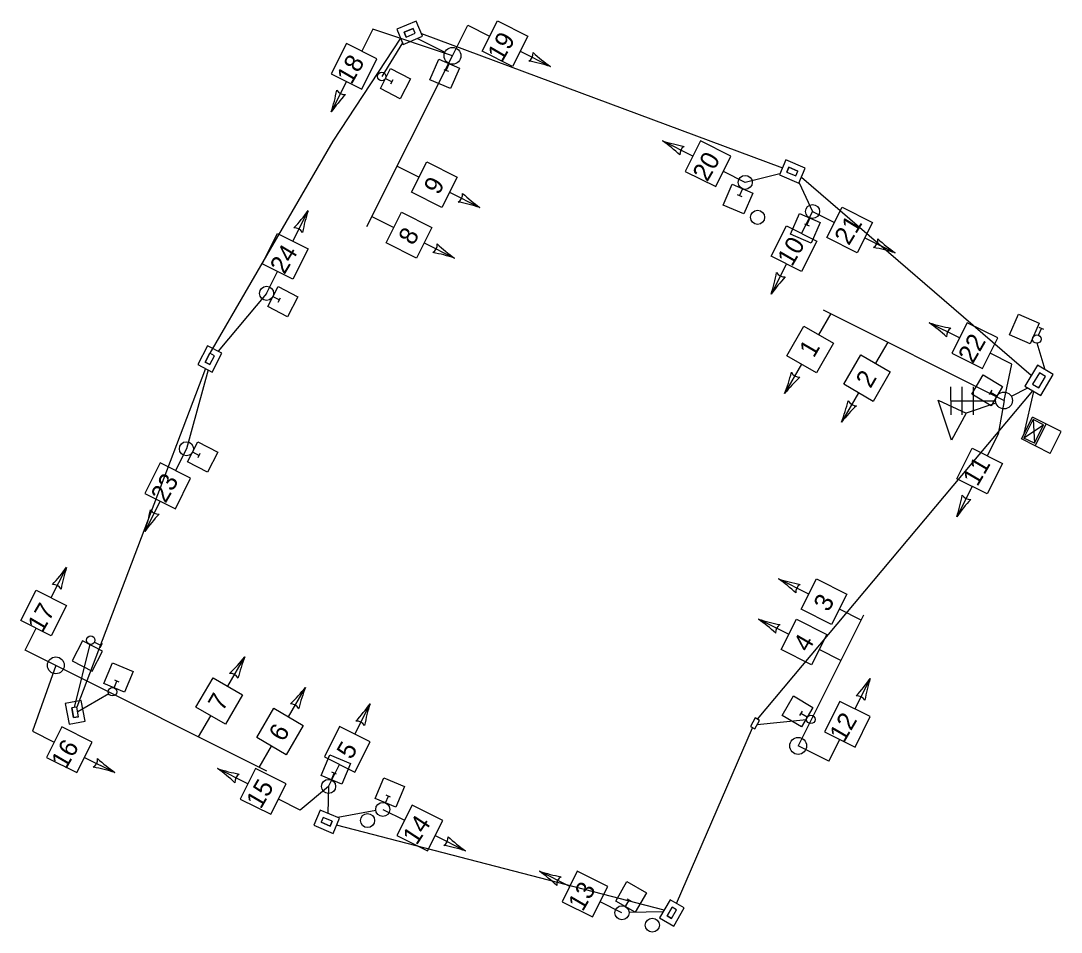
# Model space of a CAD drawing. Extents: x 998065 to 998820, y 1984965 to 1986752.
# Drawn here: x 998635.3 to 998820.4, y 1984965.1 to 1985127.2 of the extents above; entities that cross this region are included whole.
import ezdxf

# ---------------------------------------------------------------- set-up
doc = ezdxf.new("R2010")
doc.units = 0
for name, color, linetype in [('EX_ROW_Annotation', 7, 'Continuous'), ('S_CURB', 7, 'Continuous'), ('S_DRIVEWAY', 7, 'Continuous'), ('S_EDGE_PAVEMENT', 7, 'Continuous'), ('S_PAVEMENT_CROWN', 7, 'Continuous'), ('S_SHOULDER', 7, 'Continuous'), ('S_SIDEWALK', 7, 'Continuous'), ('S_WALL', 7, 'Continuous')]:
    doc.layers.add(name, color=color, linetype=linetype)

msp = doc.modelspace()

# ---------------------------------------------------------------- linework, layer by layer
at = {"layer": 'EX_ROW_Annotation'}
for centre in [(998766.4, 1985092.21), (998696.98, 1984984.92), (998747.66, 1984966.31)]:
    msp.add_circle(centre, 1.25, dxfattribs=at)
at = {"layer": 'S_CURB'}
for p, q in [((998813.35, 1985052.8), (998815.29, 1985056.67)), ((998813.79, 1985052.95), (998815.44, 1985056.23)), ((998820.42, 1985054.1), (998815.29, 1985056.67)), ((998815.44, 1985056.23), (998815.65, 1985052.02)), ((998817.3, 1985055.3), (998815.44, 1985056.23)), ((998813.8, 1985052.97), (998817.3, 1985055.3)), ((998815.65, 1985052.02), (998817.3, 1985055.3)), ((998815.8, 1985051.57), (998817.74, 1985055.44)), ((998818.48, 1985050.23), (998820.42, 1985054.1)), ((998818.48, 1985050.23), (998813.35, 1985052.8)), ((998815.65, 1985052.02), (998813.79, 1985052.95))]:
    msp.add_line(p, q, dxfattribs=at)
at = {"layer": 'S_DRIVEWAY'}
for p, q in [((998706.57, 1985124.9), (998770.84, 1985101.04)), ((998703.2, 1985123.23), (998699.51, 1985117.26)), ((998705.85, 1985124.03), (998710.75, 1985121.61)), ((998770.37, 1985099.97), (998764.19, 1985098.43)), ((998773.77, 1985098.37), (998776.18, 1985093.25)), ((998815.08, 1985064.05), (998774.18, 1985099.32)), ((998679.02, 1985078.69), (998670.38, 1985068.38)), ((998817.6, 1985065.07), (998816.14, 1985069.81)), ((998668.12, 1985065.33), (998645.23, 1985005.11)), ((998668.64, 1985065.06), (998664.74, 1985051.05)), ((998766.35, 1985002.96), (998815.37, 1985061.35)), ((998811.56, 1985060.38), (998814.48, 1985061.88)), ((998813.82, 1985053.74), (998815.57, 1985061.23)), ((998647.53, 1985016.27), (998644.78, 1985005.03)), ((998650.94, 1985007.45), (998645.4, 1985004.25)), ((998775.11, 1985002.84), (998766.34, 1985001.97)), ((998751.98, 1984970.17), (998765.51, 1985001.42)), ((998690.05, 1984990.99), (998689.91, 1984986.19)), ((998698.46, 1984986.68), (998691.67, 1984985.45)), ((998749.76, 1984969), (998691.48, 1984984.1)), ((998749.57, 1984968.69), (998743.51, 1984968.55))]:
    msp.add_line(p, q, dxfattribs=at)
msp.add_lwpolyline([(998702.84, 1985124.09), (998690.82, 1985105.74), (998668.9, 1985068.02)], dxfattribs=at)
at = {"layer": 'S_EDGE_PAVEMENT'}
for p, q in [((998696.85, 1985090.55), (998712.1, 1985120.94)), ((998778.07, 1985075.77), (998810.25, 1985059.64)), ((998785.27, 1985021.43), (998773.62, 1984998.19)), ((998679.04, 1984993.7), (998641.5, 1985012.52))]:
    msp.add_line(p, q, dxfattribs=at)
for centre, radius in [((998712.1, 1985120.94), 1.5), ((998699.51, 1985117.26), 0.75), ((998764.19, 1985098.43), 1.25), ((998776.18, 1985093.25), 1.25), ((998679.02, 1985078.69), 1.25), ((998816.09, 1985070.56), 0.75), ((998810.25, 1985059.64), 1.5), ((998664.74, 1985051.05), 1.25), ((998647.71, 1985017), 0.75), ((998641.5, 1985012.52), 1.5), ((998651.59, 1985007.82), 0.75), ((998775.86, 1985002.91), 0.75), ((998773.62, 1984998.19), 1.5), ((998690.05, 1984990.99), 1.25), ((998699.69, 1984986.9), 1.25), ((998742.26, 1984968.52), 1.25)]:
    msp.add_circle(centre, radius, dxfattribs=at)
at = {"layer": 'S_PAVEMENT_CROWN'}
for p, q in [((998712.1, 1985120.94), (998714.82, 1985126.4)), ((998714.82, 1985126.4), (998718.7, 1985124.44)), ((998697.9, 1985125.66), (998695.96, 1985121.77)), ((998712.1, 1985120.94), (998697.9, 1985125.66)), ((998724.13, 1985121.74), (998729.53, 1985119.02)), ((998693.23, 1985116.36), (998690.53, 1985110.96)), ((998754.89, 1985103.1), (998749.49, 1985105.8)), ((998702.27, 1985101.33), (998706.15, 1985099.38)), ((998764.19, 1985098.43), (998760.3, 1985100.37)), ((998711.58, 1985096.67), (998716.98, 1985093.96)), ((998683.68, 1985088), (998686.39, 1985093.39)), ((998776.18, 1985093.25), (998774.22, 1985089.37)), ((998776.18, 1985093.25), (998780.06, 1985091.3)), ((998697.75, 1985092.34), (998701.63, 1985090.38)), ((998707.06, 1985087.68), (998712.46, 1985084.96)), ((998785.48, 1985088.59), (998790.88, 1985085.88)), ((998771.52, 1985083.94), (998768.8, 1985078.55)), ((998679.02, 1985078.69), (998680.97, 1985082.57)), ((998779.44, 1985075.09), (998777.26, 1985071.33)), ((998802.35, 1985070.76), (998796.95, 1985073.46)), ((998789.56, 1985070.02), (998787.37, 1985066.26)), ((998811.65, 1985066.09), (998807.76, 1985068.03)), ((998774.23, 1985066.08), (998771.2, 1985060.85)), ((998810.25, 1985059.64), (998811.65, 1985066.09)), ((998784.35, 1985061), (998781.31, 1985055.78)), ((998810.25, 1985059.64), (998809.21, 1985053.67)), ((998809.21, 1985053.67), (998807.25, 1985049.78)), ((998664.74, 1985051.05), (998662.8, 1985047.16)), ((998804.55, 1985044.36), (998801.83, 1985038.96)), ((998660.07, 1985041.75), (998657.37, 1985036.35)), ((998640.7, 1985024.56), (998643.42, 1985029.95)), ((998775.52, 1985025.19), (998770.12, 1985027.91)), ((998784.82, 1985020.53), (998780.94, 1985022.49)), ((998771.92, 1985018.04), (998766.53, 1985020.76)), ((998636.04, 1985015.25), (998638, 1985019.13)), ((998641.5, 1985012.52), (998636.04, 1985015.25)), ((998781.23, 1985013.39), (998777.35, 1985015.34)), ((998672.1, 1985008.8), (998675.13, 1985014.02)), ((998641.5, 1985012.52), (998637.33, 1985000.82)), ((998783.75, 1985004.76), (998786.45, 1985010.17)), ((998682.91, 1985003.38), (998685.94, 1985008.6)), ((998694.72, 1985000.29), (998697.42, 1985005.69)), ((998666.89, 1984999.79), (998669.07, 1985003.55)), ((998637.33, 1985000.82), (998641.21, 1984998.88)), ((998779.07, 1984995.46), (998781.01, 1984999.35)), ((998677.7, 1984994.37), (998679.88, 1984998.13)), ((998779.07, 1984995.46), (998773.62, 1984998.19)), ((998646.63, 1984996.15), (998652.03, 1984993.45)), ((998690.05, 1984990.99), (998691.99, 1984994.88)), ((998675.7, 1984991.46), (998670.29, 1984994.16)), ((998690.05, 1984990.99), (998685, 1984986.78)), ((998685, 1984986.78), (998681.11, 1984988.72)), ((998699.69, 1984986.9), (998703.58, 1984984.96)), ((998708.99, 1984982.23), (998714.39, 1984979.53)), ((998732.96, 1984973.19), (998727.56, 1984975.89)), ((998742.26, 1984968.52), (998738.37, 1984970.46))]:
    msp.add_line(p, q, dxfattribs=at)
for points in [[(998717.35, 1985121.75), (998720.08, 1985127.16), (998725.49, 1985124.44), (998722.76, 1985119.02)], [(998698.66, 1985120.42), (998693.23, 1985123.14), (998690.52, 1985117.71), (998695.95, 1985115)], [(998758.95, 1985097.67), (998761.66, 1985103.1), (998756.24, 1985105.81), (998753.53, 1985100.38)], [(998704.8, 1985096.68), (998707.52, 1985102.1), (998712.94, 1985099.37), (998710.21, 1985093.96)], [(998700.28, 1985087.69), (998703, 1985093.11), (998708.42, 1985090.38), (998705.69, 1985084.96)], [(998778.7, 1985088.6), (998781.43, 1985094.02), (998786.84, 1985091.29), (998784.12, 1985085.88)], [(998683.67, 1985081.22), (998678.25, 1985083.94), (998680.98, 1985089.36), (998686.39, 1985086.63)], [(998771.53, 1985090.72), (998776.94, 1985088), (998774.22, 1985082.58), (998768.8, 1985085.31)], [(998774.65, 1985072.85), (998779.89, 1985069.8), (998776.85, 1985064.56), (998771.6, 1985067.6)], [(998806.41, 1985065.33), (998809.12, 1985070.76), (998803.7, 1985073.47), (998800.99, 1985068.04)], [(998784.76, 1985067.77), (998790.01, 1985064.73), (998786.96, 1985059.48), (998781.72, 1985062.53)], [(998804.56, 1985051.14), (998809.98, 1985048.41), (998807.25, 1985043), (998801.83, 1985045.72)], [(998665.5, 1985045.82), (998660.07, 1985048.53), (998657.36, 1985043.1), (998662.79, 1985040.39)], [(998782.3, 1985025.18), (998779.57, 1985019.77), (998774.16, 1985022.49), (998776.88, 1985027.91)], [(998640.69, 1985017.78), (998635.27, 1985020.5), (998638, 1985025.92), (998643.42, 1985023.19)], [(998778.7, 1985018.03), (998775.98, 1985012.62), (998770.56, 1985015.34), (998773.29, 1985020.76)], [(998671.68, 1985002.03), (998666.44, 1985005.08), (998669.48, 1985010.32), (998674.73, 1985007.27)], [(998778.32, 1985000.7), (998783.74, 1984997.99), (998786.45, 1985003.41), (998781.03, 1985006.12)], [(998682.49, 1984996.61), (998677.25, 1984999.66), (998680.29, 1985004.9), (998685.54, 1985001.85)], [(998642.56, 1985001.58), (998639.85, 1984996.15), (998645.27, 1984993.44), (998647.99, 1984998.87)], [(998689.29, 1984996.22), (998694.72, 1984993.51), (998697.43, 1984998.94), (998692, 1985001.65)], [(998679.76, 1984986.03), (998682.47, 1984991.45), (998677.05, 1984994.16), (998674.34, 1984988.74)], [(998704.92, 1984987.66), (998702.21, 1984982.23), (998707.64, 1984979.52), (998710.35, 1984984.95)], [(998737.02, 1984967.76), (998739.73, 1984973.19), (998734.31, 1984975.9), (998731.6, 1984970.47)]]:
    msp.add_lwpolyline(points, close=True, dxfattribs=at)
for centre, radius, start, end in [((998724.82, 1985121.39), 1.63, 301.4366, 5.1312), ((998746.57, 1985143.07), 29.47, 226.9375, 234.6756), ((998720.37, 1985091.01), 29.47, 71.8922, 79.6303), ((998662.49, 1985120.04), 29.47, 342.0542, 349.7923), ((998714.62, 1985093.98), 29.47, 137.0994, 144.8375), ((998692.88, 1985115.67), 1.63, 211.5985, 275.2932), ((998732.51, 1985081.71), 29.47, 47.0994, 54.8375), ((998758.57, 1985133.84), 29.47, 252.0542, 259.7923), ((998754.2, 1985103.45), 1.63, 121.5985, 185.2932), ((998712.27, 1985096.32), 1.63, 301.4366, 5.1312), ((998734.02, 1985118), 29.47, 226.9375, 234.6756), ((998707.82, 1985065.94), 29.47, 71.8922, 79.6303), ((998662.35, 1985110.44), 29.47, 316.9375, 324.6756), ((998714.41, 1985084.23), 29.47, 161.8922, 169.6303), ((998684.03, 1985088.69), 1.63, 31.4366, 95.1312), ((998707.75, 1985087.33), 1.63, 301.4366, 5.1312), ((998729.5, 1985109.01), 29.47, 226.9375, 234.6756), ((998786.18, 1985088.24), 1.63, 301.4366, 5.1312), ((998807.92, 1985109.92), 29.47, 226.9375, 234.6756), ((998703.3, 1985056.95), 29.47, 71.8922, 79.6303), ((998781.72, 1985057.86), 29.47, 71.8922, 79.6303), ((998740.79, 1985087.71), 29.47, 341.8922, 349.6303), ((998792.85, 1985061.5), 29.47, 136.9375, 144.6756), ((998771.17, 1985083.25), 1.63, 211.4366, 275.1312), ((998779.97, 1985049.37), 29.47, 47.0994, 54.8375), ((998806.03, 1985101.5), 29.47, 252.0542, 259.7923), ((998801.66, 1985071.11), 1.63, 121.5985, 185.2932), ((998743.79, 1985071.68), 29.47, 338.4472, 346.1853), ((998794.18, 1985042.4), 29.47, 133.4924, 141.2306), ((998773.84, 1985065.41), 1.63, 207.9916, 271.6862), ((998753.9, 1985066.61), 29.47, 338.4472, 346.1853), ((998783.96, 1985060.33), 1.63, 207.9916, 271.6862), ((998804.29, 1985037.33), 29.47, 133.4924, 141.2306), ((998773.82, 1985048.12), 29.47, 341.8922, 349.6303), ((998804.2, 1985043.67), 1.63, 211.4366, 275.1312), ((998825.88, 1985021.92), 29.47, 136.9375, 144.6756), ((998629.33, 1985045.43), 29.47, 342.0542, 349.7923), ((998681.46, 1985019.37), 29.47, 137.0994, 144.8375), ((998659.72, 1985041.06), 1.63, 211.5985, 275.2932), ((998619.37, 1985047), 29.47, 316.9375, 324.6756), ((998671.43, 1985020.79), 29.47, 161.8922, 169.6303), ((998779.28, 1985055.92), 29.47, 251.8922, 259.6303), ((998753.08, 1985003.86), 29.47, 46.9375, 54.6756), ((998641.05, 1985025.25), 1.63, 31.4366, 95.1312), ((998774.82, 1985025.54), 1.63, 121.4366, 185.1312), ((998775.69, 1985048.77), 29.47, 251.8922, 259.6303), ((998749.49, 1984996.71), 29.47, 46.9375, 54.6756), ((998771.23, 1985018.39), 1.63, 121.4366, 185.1312), ((998652.15, 1985032.48), 29.47, 313.4924, 321.2306), ((998702.54, 1985003.2), 29.47, 158.4472, 166.1853), ((998672.49, 1985009.47), 1.63, 27.9916, 91.6862), ((998762.35, 1985027.14), 29.47, 317.0994, 324.8375), ((998814.48, 1985001.08), 29.47, 162.0542, 169.7923), ((998662.97, 1985027.06), 29.47, 313.4924, 321.2306), ((998713.36, 1984997.78), 29.47, 158.4472, 166.1853), ((998683.3, 1985004.05), 1.63, 27.9916, 91.6862), ((998673.33, 1985022.67), 29.47, 317.0994, 324.8375), ((998725.46, 1984996.61), 29.47, 162.0542, 169.7923), ((998784.09, 1985005.45), 1.63, 31.5985, 95.2932), ((998695.07, 1985000.98), 1.63, 31.5985, 95.2932), ((998647.32, 1984995.8), 1.63, 301.5985, 5.2932), ((998669, 1985017.54), 29.47, 227.0994, 234.8375), ((998642.95, 1984965.41), 29.47, 72.0542, 79.7923), ((998653.32, 1984970.06), 29.47, 47.0994, 54.8375), ((998679.37, 1985022.19), 29.47, 252.0542, 259.7923), ((998675, 1984991.8), 1.63, 121.5985, 185.2932), ((998709.68, 1984981.88), 1.63, 301.5985, 5.2932), ((998731.37, 1985003.62), 29.47, 227.0994, 234.8375), ((998705.31, 1984951.49), 29.47, 72.0542, 79.7923), ((998710.58, 1984951.8), 29.47, 47.0994, 54.8375), ((998736.64, 1985003.93), 29.47, 252.0542, 259.7923), ((998732.27, 1984973.54), 1.63, 121.5985, 185.2932)]:
    msp.add_arc(centre, radius, start, end, dxfattribs=at)
at = {"layer": 'S_SHOULDER'}
for points in [[(998701.09, 1985118.7), (998704.65, 1985116.86), (998702.81, 1985113.31), (998699.26, 1985115.14)], [(998713.34, 1985118.77), (998711.75, 1985115.1), (998708.08, 1985116.69), (998709.67, 1985120.36)], [(998765.53, 1985096.49), (998763.94, 1985092.82), (998760.27, 1985094.4), (998761.85, 1985098.08)], [(998777.51, 1985091.31), (998775.92, 1985087.64), (998772.25, 1985089.23), (998773.84, 1985092.9)], [(998681.05, 1985079.89), (998684.6, 1985078.05), (998682.76, 1985074.5), (998679.21, 1985076.34)], [(998814.9, 1985069.71), (998811.23, 1985071.3), (998812.82, 1985074.97), (998816.49, 1985073.38)], [(998807.94, 1985058.69), (998804.51, 1985060.74), (998806.56, 1985064.18), (998809.99, 1985062.12)], [(998666.77, 1985052.25), (998670.32, 1985050.42), (998668.49, 1985046.86), (998664.93, 1985048.7)], [(998646.26, 1985016.9), (998644.42, 1985013.35), (998647.97, 1985011.51), (998649.81, 1985015.07)], [(998650.04, 1985009.29), (998651.6, 1985012.97), (998655.28, 1985011.41), (998653.72, 1985007.73)], [(998774.19, 1985001.58), (998770.76, 1985003.63), (998772.81, 1985007.07), (998776.24, 1985005.01)], [(998688.7, 1984992.92), (998690.26, 1984996.6), (998693.94, 1984995.04), (998692.38, 1984991.36)], [(998698.34, 1984988.83), (998699.9, 1984992.52), (998703.58, 1984990.96), (998702.02, 1984987.27)], [(998741.16, 1984970.6), (998743.15, 1984974.06), (998746.62, 1984972.06), (998744.62, 1984968.6)]]:
    msp.add_lwpolyline(points, close=True, dxfattribs=at)
at = {"layer": 'S_SIDEWALK'}
for p, q in [((998705.66, 1985127.11), (998702.19, 1985125.68)), ((998706.77, 1985124.41), (998705.66, 1985127.11)), ((998702.19, 1985125.68), (998703.3, 1985122.98)), ((998703.3, 1985122.98), (998706.77, 1985124.41)), ((998703.5, 1985125.13), (998705.11, 1985125.8)), ((998705.11, 1985125.8), (998703.5, 1985125.13)), ((998703.85, 1985124.28), (998703.5, 1985125.13)), ((998703.5, 1985125.13), (998703.85, 1985124.28)), ((998703.85, 1985124.28), (998705.46, 1985124.95)), ((998703.85, 1985124.28), (998705.46, 1985124.95)), ((998705.46, 1985124.95), (998705.11, 1985125.8)), ((998705.46, 1985124.95), (998705.11, 1985125.8)), ((998711.5, 1985119.56), (998710.98, 1985118.36)), ((998700.17, 1985116.92), (998701.35, 1985116.31)), ((998710.58, 1985118.53), (998711.38, 1985118.18)), ((998701.14, 1985115.93), (998701.55, 1985116.7)), ((998771.44, 1985102.43), (998770.28, 1985099.75)), ((998774.88, 1985100.95), (998771.44, 1985102.43)), ((998771.59, 1985100.27), (998771.96, 1985101.12)), ((998771.96, 1985101.12), (998771.59, 1985100.27)), ((998771.59, 1985100.27), (998773.2, 1985099.58)), ((998771.59, 1985100.27), (998773.2, 1985099.58)), ((998771.96, 1985101.12), (998773.57, 1985100.42)), ((998773.57, 1985100.42), (998771.96, 1985101.12)), ((998773.2, 1985099.58), (998773.57, 1985100.42)), ((998773.2, 1985099.58), (998773.57, 1985100.42)), ((998773.72, 1985098.26), (998774.88, 1985100.95)), ((998770.28, 1985099.75), (998773.72, 1985098.26)), ((998763.69, 1985097.28), (998763.17, 1985096.07)), ((998762.77, 1985096.25), (998763.57, 1985095.9)), ((998774.75, 1985091.07), (998775.55, 1985090.72)), ((998775.68, 1985092.1), (998775.15, 1985090.9)), ((998680.13, 1985078.11), (998681.3, 1985077.51)), ((998681.1, 1985077.12), (998681.5, 1985077.89)), ((998816.39, 1985071.25), (998816.91, 1985072.46)), ((998817.31, 1985072.28), (998816.51, 1985072.63)), ((998668.47, 1985069.37), (998666.75, 1985066.03)), ((998671.07, 1985068.03), (998668.47, 1985069.37)), ((998668.1, 1985066.46), (998668.9, 1985068.02)), ((998668.9, 1985068.02), (998668.1, 1985066.46)), ((998669.72, 1985067.6), (998668.9, 1985068.02)), ((998669.72, 1985067.6), (998668.9, 1985068.02)), ((998668.92, 1985066.04), (998669.72, 1985067.6)), ((998668.92, 1985066.04), (998669.72, 1985067.6)), ((998669.35, 1985064.69), (998671.07, 1985068.03)), ((998666.75, 1985066.03), (998669.35, 1985064.69)), ((998668.92, 1985066.04), (998668.1, 1985066.46)), ((998668.1, 1985066.46), (998668.92, 1985066.04)), ((998816.19, 1985065.9), (998813.97, 1985062.19)), ((998819, 1985064.23), (998816.19, 1985065.9)), ((998816.54, 1985064.53), (998815.34, 1985062.53)), ((998816.43, 1985061.88), (998817.63, 1985063.88)), ((998817.63, 1985063.88), (998816.54, 1985064.53)), ((998816.77, 1985060.51), (998819, 1985064.23)), ((998808.06, 1985061.46), (998807.61, 1985060.71)), ((998813.97, 1985062.19), (998816.77, 1985060.51)), ((998815.34, 1985062.53), (998816.43, 1985061.88)), ((998800.91, 1985052.56), (998798.53, 1985059.68)), ((998798.53, 1985059.68), (998803.51, 1985057.39)), ((998808.97, 1985060.41), (998807.84, 1985061.08)), ((998808.59, 1985059.08), (998803.51, 1985057.39)), ((998803.51, 1985057.39), (998800.91, 1985052.56)), ((998665.85, 1985050.47), (998667.02, 1985049.87)), ((998666.82, 1985049.48), (998667.22, 1985050.26)), ((998648.38, 1985016.65), (998649.55, 1985016.05)), ((998649.75, 1985016.43), (998649.35, 1985015.66)), ((998651.88, 1985008.51), (998652.39, 1985009.72)), ((998652.8, 1985009.55), (998651.99, 1985009.9)), ((998646.03, 1985006.28), (998643.16, 1985005.74)), ((998643.16, 1985005.74), (998643.86, 1985002.05)), ((998646.73, 1985002.6), (998646.03, 1985006.28)), ((998645.23, 1985005.11), (998644.33, 1985004.94)), ((998645.23, 1985005.11), (998644.33, 1985004.94)), ((998644.65, 1985003.22), (998644.33, 1985004.94)), ((998644.33, 1985004.94), (998644.65, 1985003.22)), ((998645.56, 1985003.39), (998645.23, 1985005.11)), ((998645.56, 1985003.39), (998645.23, 1985005.11)), ((998774.31, 1985004.35), (998773.86, 1985003.6)), ((998775.22, 1985003.3), (998774.09, 1985003.97)), ((998643.86, 1985002.05), (998646.73, 1985002.6)), ((998645.56, 1985003.39), (998644.65, 1985003.22)), ((998644.65, 1985003.22), (998645.56, 1985003.39)), ((998765.95, 1985003.18), (998765.11, 1985001.64)), ((998765.91, 1985001.2), (998766.76, 1985002.74)), ((998766.76, 1985002.74), (998765.95, 1985003.18)), ((998765.11, 1985001.64), (998765.91, 1985001.2)), ((998690.54, 1984992.14), (998691.05, 1984993.35)), ((998691.45, 1984993.18), (998690.65, 1984993.52)), ((998700.18, 1984988.05), (998700.69, 1984989.27)), ((998701.09, 1984989.1), (998700.29, 1984989.44)), ((998688.54, 1984986.77), (998687.4, 1984984.08)), ((998691.99, 1984985.31), (998688.54, 1984986.77)), ((998689.07, 1984985.46), (998688.71, 1984984.61)), ((998689.07, 1984985.46), (998688.71, 1984984.61)), ((998690.68, 1984984.78), (998689.07, 1984985.46)), ((998690.68, 1984984.78), (998689.07, 1984985.46)), ((998690.85, 1984982.62), (998691.99, 1984985.31)), ((998687.4, 1984984.08), (998690.85, 1984982.62)), ((998690.32, 1984983.93), (998688.71, 1984984.61)), ((998688.71, 1984984.61), (998690.32, 1984983.93)), ((998690.68, 1984984.78), (998690.32, 1984983.93)), ((998690.32, 1984983.93), (998690.68, 1984984.78)), ((998742.89, 1984969.6), (998743.55, 1984970.74)), ((998743.92, 1984970.52), (998743.17, 1984970.96)), ((998750.82, 1984970.84), (998748.94, 1984967.59)), ((998753.34, 1984969.38), (998750.82, 1984970.84)), ((998750.31, 1984967.96), (998751.18, 1984969.48)), ((998751.18, 1984969.48), (998750.31, 1984967.96)), ((998751.1, 1984967.5), (998751.98, 1984969.02)), ((998751.1, 1984967.5), (998751.98, 1984969.02)), ((998751.98, 1984969.02), (998751.18, 1984969.48)), ((998751.98, 1984969.02), (998751.18, 1984969.48)), ((998751.47, 1984966.13), (998753.34, 1984969.38)), ((998748.94, 1984967.59), (998751.47, 1984966.13)), ((998751.1, 1984967.5), (998750.31, 1984967.96)), ((998750.31, 1984967.96), (998751.1, 1984967.5))]:
    msp.add_line(p, q, dxfattribs=at)
at = {"layer": 'S_WALL'}
for p, q in [((998800.75, 1985062.06), (998800.76, 1985057.06)), ((998802.75, 1985062.06), (998802.76, 1985057.06)), ((998804.75, 1985062.07), (998804.76, 1985057.07)), ((998800.76, 1985059.56), (998808.76, 1985059.57))]:
    msp.add_line(p, q, dxfattribs=at)

# ---------------------------------------------------------------- texts
at = {"layer": 'S_PAVEMENT_CROWN'}
for s, rotation, p in [('19', 59.8389, (998720.93, 1985119.71)), ('18', 59.8389, (998694.11, 1985115.69)), ('20', 59.8389, (998757.43, 1985098.39)), ('9', 59.8389, (998709.6, 1985096.05)), ('21', 58.6395, (998782.62, 1985087.06)), ('8', 59.8389, (998705.08, 1985087.06)), ('24', 59.1062, (998682.19, 1985081.91)), ('10', 59.8389, (998772.51, 1985083.3)), ('22', 60.0057, (998804.71, 1985066.05)), ('1', 59.8389, (998776.4, 1985067.08)), ('2', 59.8389, (998786.49, 1985061.65)), ('11', 59.8389, (998805.51, 1985044.19)), ('23', 59.8389, (998661.03, 1985041.22)), ('3', 60.5812, (998778.99, 1985021.88)), ('17', 59.8389, (998639.07, 1985018.14)), ('4', 59.8389, (998775.37, 1985014.71)), ('7', 59.8389, (998671.21, 1985004.2)), ('12', 59.8389, (998781.79, 1984998.67)), ('6', 59.8389, (998682.02, 1984998.78)), ('16', 59.8389, (998643.29, 1984993.89)), ('5', 59.8389, (998694.1, 1984995.61)), ('15', 59.7464, (998677.98, 1984986.82)), ('14', 56.7269, (998705.71, 1984980.4)), ('13', 59.8389, (998735.27, 1984968.59))]:
    msp.add_text(s, height=3.25, rotation=rotation, dxfattribs=at).set_placement(p)

doc.saveas('drawing.dxf')
